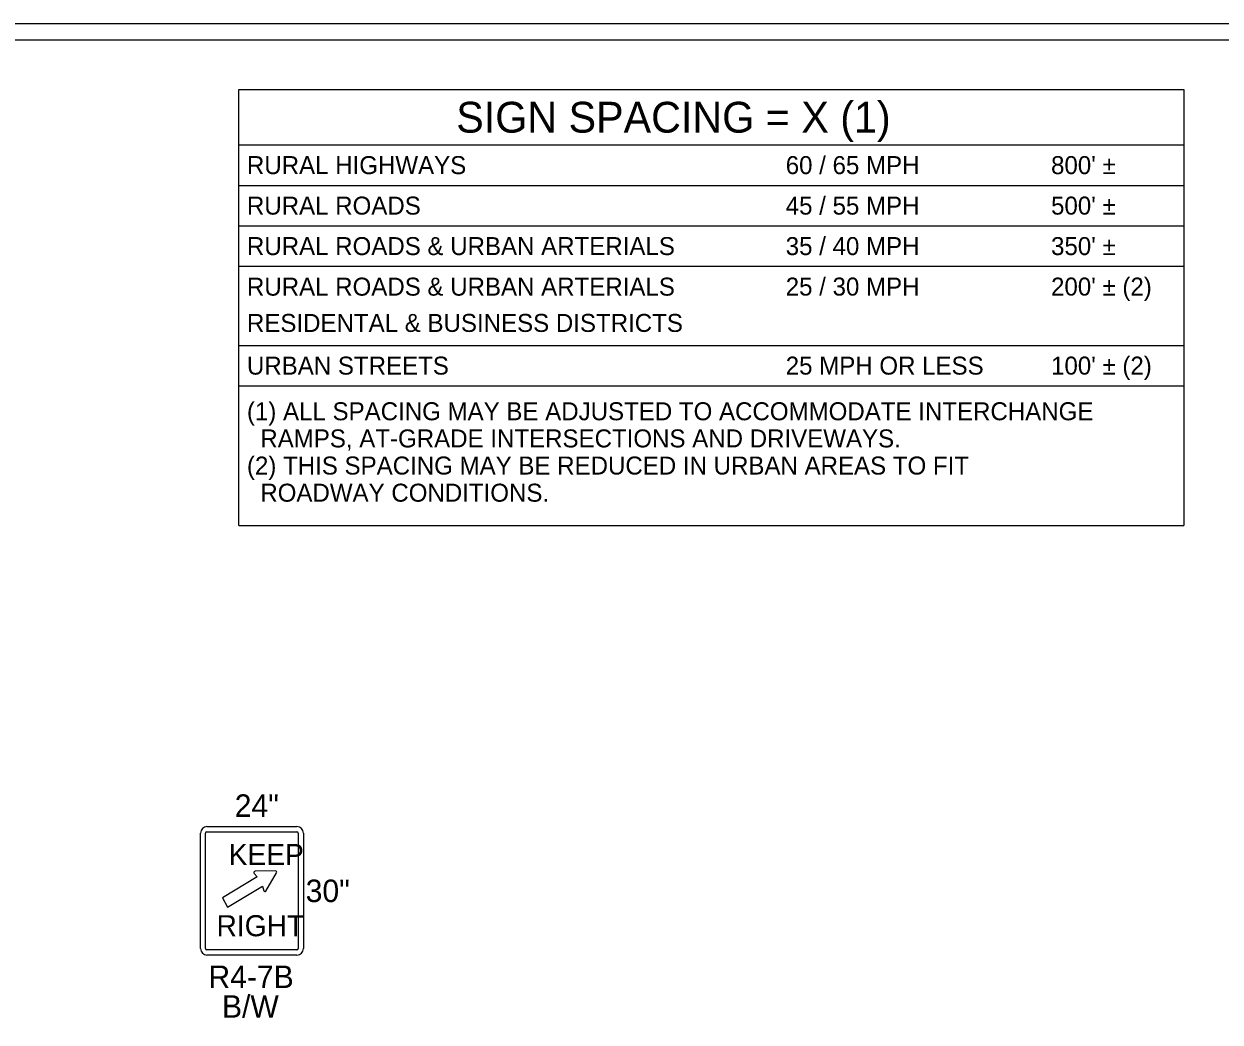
# Model space of a CAD drawing. Extents: x 99988 to 100172, y 99995 to 100047.
# Drawn here: x 100005.575 to 100010.227, y 100006.555 to 100010.437 of the extents above; entities that cross this region are included whole.
import ezdxf

# ---------------------------------------------------------------- set-up
doc = ezdxf.new("R2010")
doc.units = 0
for name, color, linetype in [('SH_GI_PlotLimits', 7, 'Continuous'), ('SH_GI_SheetBorder', 7, 'Continuous'), ('SH_TI_SignSpacing35to70Note', 7, 'Continuous'), ('TR_SN_RegulatorySigns', 7, 'Continuous')]:
    doc.layers.add(name, color=color, linetype=linetype)

msp = doc.modelspace()

# ---------------------------------------------------------------- linework, layer by layer
at = {"layer": 'SH_GI_PlotLimits'}
msp.add_lwpolyline([(99999.3125, 99999.9375), (100015.8125, 99999.9375), (100015.8125, 100010.4375), (99999.3125, 100010.4375)], close=True, dxfattribs=at)
at = {"layer": 'SH_GI_SheetBorder'}
msp.add_line((100000, 100010.375), (100015.75, 100010.375), dxfattribs=at)
at = {"layer": 'SH_TI_SignSpacing35to70Note'}
for p, q in [((100006.411, 100009.9674), (100010.0865, 100009.9674)), ((100006.411, 100009.8096), (100010.0865, 100009.8096)), ((100006.411, 100009.6522), (100010.0865, 100009.6522)), ((100006.411, 100009.4947), (100010.0865, 100009.4947)), ((100006.411, 100009.1873), (100010.0865, 100009.1873)), ((100006.411, 100009.0299), (100010.0865, 100009.0299)), ((100006.411, 100008.4863), (100010.0865, 100008.4863))]:
    msp.add_line(p, q, dxfattribs=at)
for points in [[(100006.411, 100009.9674), (100006.411, 100010.1819), (100010.0865, 100010.1819), (100010.0865, 100009.9654)], [(100006.411, 100008.4863), (100006.411, 100009.9654)], [(100010.0865, 100009.9654), (100010.0865, 100008.4863)]]:
    msp.add_lwpolyline(points, dxfattribs=at)
at = {"layer": 'TR_SN_RegulatorySigns'}
for p, q in [((100006.2864, 100007.3159), (100006.6364, 100007.3159)), ((100006.2864, 100007.2954), (100006.6364, 100007.2954)), ((100006.2614, 100006.8419), (100006.2614, 100007.2899)), ((100006.2811, 100006.8419), (100006.2811, 100007.2899)), ((100006.6417, 100007.2899), (100006.6417, 100006.8419)), ((100006.6614, 100007.2899), (100006.6614, 100006.8419)), ((100006.4823, 100007.1204), (100006.3464, 100007.0386)), ((100006.4701, 100007.1338), (100006.4823, 100007.1204)), ((100006.5534, 100007.1435), (100006.4734, 100007.1419)), ((100006.5158, 100007.0651), (100006.5574, 100007.1362)), ((100006.3665, 100007.0023), (100006.5025, 100007.0841)), ((100006.5025, 100007.0841), (100006.5075, 100007.0662)), ((100006.3464, 100007.0386), (100006.3665, 100007.0023)), ((100006.6364, 100006.8364), (100006.2864, 100006.8364)), ((100006.6364, 100006.8159), (100006.2864, 100006.8159))]:
    msp.add_line(p, q, dxfattribs=at)
for centre, major_axis, ratio, start_param, end_param in [((100006.2864, 100007.2898), (0, -0.026), 0.960021, 3.141593, 4.712389), ((100006.2864, 100007.2898), (0, -0.00555), 0.960051, 3.141593, 4.712389), ((100006.6364, 100007.2898), (0, 0.026), 0.960021, 4.712389, 6.283185), ((100006.6364, 100007.2898), (0, 0.00555), 0.960051, 4.712389, 6.283185), ((100006.4735, 100007.1371), (0, 0.00478), 0.96, 0.019017, 2.328605), ((100006.5535, 100007.1387), (0, -0.00478), 0.96, 1.023619, 3.16061), ((100006.5119, 100007.0676), (0, -0.00478), 0.96, 4.99813, 7.306805), ((100006.2864, 100006.8419), (0, -0.026), 0.960021, 4.712389, 6.283185), ((100006.2864, 100006.8419), (0, -0.00555), 0.960051, 4.712389, 6.283185), ((100006.6364, 100006.8419), (0, -0.00555), 0.960051, 0, 1.570796), ((100006.6364, 100006.8419), (0, -0.026), 0.960021, 0, 1.570796)]:
    msp.add_ellipse(centre, major_axis=major_axis, ratio=ratio, start_param=start_param, end_param=end_param, dxfattribs=at)

# ---------------------------------------------------------------- texts
at = {"layer": 'SH_TI_SignSpacing35to70Note'}
for s, height, p in [('SIGN SPACING = X (1)', 0.12, (100007.2561, 100010.0146)), ('RURAL HIGHWAYS', 0.07, (100006.442, 100009.8533)), ('60 / 65 MPH', 0.07, (100008.5376, 100009.8533)), ("800' ±", 0.07, (100009.5696, 100009.8533)), ('RURAL ROADS', 0.07, (100006.442, 100009.6959)), ('45 / 55 MPH', 0.07, (100008.5376, 100009.6959)), ("500' ±", 0.07, (100009.5696, 100009.6959)), ('RURAL ROADS & URBAN ARTERIALS', 0.07, (100006.442, 100009.5384)), ('35 / 40 MPH', 0.07, (100008.5376, 100009.5384)), ("350' ± ", 0.07, (100009.5696, 100009.5384)), ('RURAL ROADS & URBAN ARTERIALS', 0.07, (100006.442, 100009.3807)), ('25 / 30 MPH', 0.07, (100008.5376, 100009.381)), ("200' ± (2)", 0.07, (100009.5696, 100009.381)), ('RESIDENTAL & BUSINESS DISTRICTS', 0.07, (100006.442, 100009.2396)), ('URBAN STREETS', 0.07, (100006.442, 100009.0736)), ('25 MPH OR LESS', 0.07, (100008.5376, 100009.0736)), ("100' ± (2) ", 0.07, (100009.5696, 100009.0736)), ('(1) ALL SPACING MAY BE ADJUSTED TO ACCOMMODATE INTERCHANGE ', 0.07, (100006.442, 100008.896)), ('  RAMPS, AT-GRADE INTERSECTIONS AND DRIVEWAYS.', 0.07, (100006.442, 100008.7904)), ('(2) THIS SPACING MAY BE REDUCED IN URBAN AREAS TO FIT  ', 0.07, (100006.442, 100008.6849)), ('  ROADWAY CONDITIONS.', 0.07, (100006.442, 100008.5793))]:
    msp.add_text(s, height=height, dxfattribs=at).set_placement(p)
at = {"layer": 'TR_SN_RegulatorySigns'}
for s, height, p in [('24"', 0.0875, (100006.3945, 100007.3534)), ('KEEP', 0.08197, (100006.371, 100007.1658)), ('30"', 0.0875, (100006.6705, 100007.0221)), ('RIGHT', 0.08197, (100006.3237, 100006.8892)), ('R4-7B', 0.0875, (100006.2922, 100006.6878)), ('B/W', 0.0875, (100006.345, 100006.5723))]:
    msp.add_text(s, height=height, dxfattribs=at).set_placement(p)

doc.saveas('drawing.dxf')
